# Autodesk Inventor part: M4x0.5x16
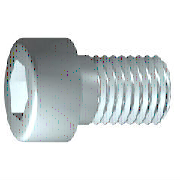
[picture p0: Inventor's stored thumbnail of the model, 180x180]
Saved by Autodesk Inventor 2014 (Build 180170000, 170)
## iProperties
IsCustomPart: 1
Company: 한국ATC센터
Created: 2009-02
Part Number: M4x0.5x16
Material: 강철, 연강
Description: 6각머리 태핑 나사
Document SubType Name: Modeling
Standard: KS B 1003
Designer: KYOUNG IL JANG
Standards Organization: KS
Language: ko-KR
Size Designation: M 4 x 16
Categories: <MemberInstance><Categories><Category DisplayName="조임쇠" InternalName="e4da775c-781d-43d5-af7c-5136215cf5a6" Mnemonic="FSTN"><Category DisplayName="볼트" InternalN
Density: 7.86 g/cm^3
Mass: 2.62973 g
Surface Area: 3.81119 cm^2
Volume: 0.334572 cm^3
Vendor: CBT Solutions
Appearance: 연마 - 진회색
Author: KYOUNG IL JANG
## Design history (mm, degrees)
sketch "스케치1"
  geometry: L1 (-1, 0)-(16, 0); L2 (16, 0)-(16, 2); L3 (16, 2)-(1.75, 2); L4 (1.75, 2)-(1.32, 2); L5 (1.32, 2)-(0, 2); L6 (0, 2)-(0, 3.5); L7 (0, 3.5)-(-4, 3.5); L8 (-4, 3.5)-(-4, 1.732); L9 (-4, 1.732)-(-2, 1.732); L10 (-2, 1.732)-(-1, 0); L11 (-8, 0)-(20, 0) reference; L12 (0, -0.7)-(0, 4.2) reference; L13 (1.75, 2)-(0, 2)
  constraints: 22 end point, 6 parallel, 2 collinear, 2 perpendicular, 1 horizontal, 1 point on line
  dimensions: "d1" = 14.25 distance from line of L3.end L2 (= GEL); "d2" = 0.42952 distance of L4.end L3.end (computed from GAL); "d3" = 4 distance between parallel lines of L8 L6 (= KOH); "d4" = 2 distance of L8.end L9.end (= INTI); "d5" = 60 deg angle of L10 L1; "d6" = 4 diameter of L3 L1 (= GD); "d7" = 4 diameter of L5 L1 (= BDM); "d8" = 3.4641 diameter of L9 L1 (= 1.1547 x SW); "d9" = 7 diameter of L7 L1 (= KOD); "d26" = 16 distance between parallel lines of L12 L2 (= NLG)
revolve "본체" sketch "스케치1" stored, may be unused: angle "d10" = 90 deg
sketch "스케치2"
  geometry: L1 (0, -4.9)-(0, 4.9) reference; L2 (-4.9, 0)-(4.9, 0) reference; L3 (1.732, 0)-(0.866, -1.5); L4 (0.866, -1.5)-(-0.866, -1.5); L5 (-0.866, -1.5)-(-1.732, 0); L6 (-1.732, 0)-(-0.866, 1.5); L7 (-0.866, 1.5)-(0.866, 1.5); L8 (0.866, 1.5)-(1.732, 0); 2 further points
  constraints: 12 end point, 1 coincident, 1 horizontal alignment, 1 point on line, 12 other
extrude "슬롯" join sketch "스케치2" stored distance "d11" = 10; taper "d12" = 0 deg
workplane "Work Plane1"
fillet "Fillet2" dims "d30" = 0.1 (= R)
body "Solid1"
fillet "모깎기1" dims "d17" = 0.4 (= RR)
feature "스레드" dims "d13" = 14.25 (= GEL), "d14" = 0
chamfer "모따기1" distance "d15" = 0.42941 (= -0.5 x SPD + 0.5 x GD); stored, may be unused: second distance "d16" = 0.42941 (= GUL), angle "d27" = 45 deg
other parameters: "GD" = 4 (= NND) [user parameter; used in 2 equation terms], "NLG" = 16 [user parameter; used in 1 equation term], "GEL" = 14.25 [user parameter; used in 2 equation terms], "KOD" = 7 [user parameter; used in 1 equation term], "KOH" = 4 [user parameter; used in 1 equation term], "INTI" = 2 [user parameter; used in 1 equation term], "GAL" = 0.42941 (= 0.61345 x PTC) [user parameter; used in 1 equation term], "GUL" = 0.42941 (= 0.61345 x PTC) [user parameter; used in 1 equation term], "BDM" = 4 (= NND) [user parameter; used in 1 equation term], "SW" = 3 [user parameter; used in 2 equation terms], "RR" = 0.4 [user parameter; used in 1 equation term], "SPD" = 3.14117 (= NND - 1.2269 x PTC) [user parameter; used in 1 equation term], "d19" = 0, "d28" = 0, "d29" = 0, "R" = 0.1 [user parameter; used in 1 equation term], "PHH" = 0.2 [user parameter], "GD1" = 3.14117 (= THREADDIA - 1.2269 x PTC) [user parameter], "THREADDIA" = 4 [user parameter; used in 1 equation term], "FAWI" = 45 deg [user parameter], "TPU" = 14.28571 (computed from PTC) [user parameter], "PTC" = 0.7 [user parameter; used in 5 equation terms], "NND" = 4 [user parameter; used in 3 equation terms], "TOA" = 30 deg [user parameter], "E0" = 3.465 (= 1.155 x SW) [user parameter]
